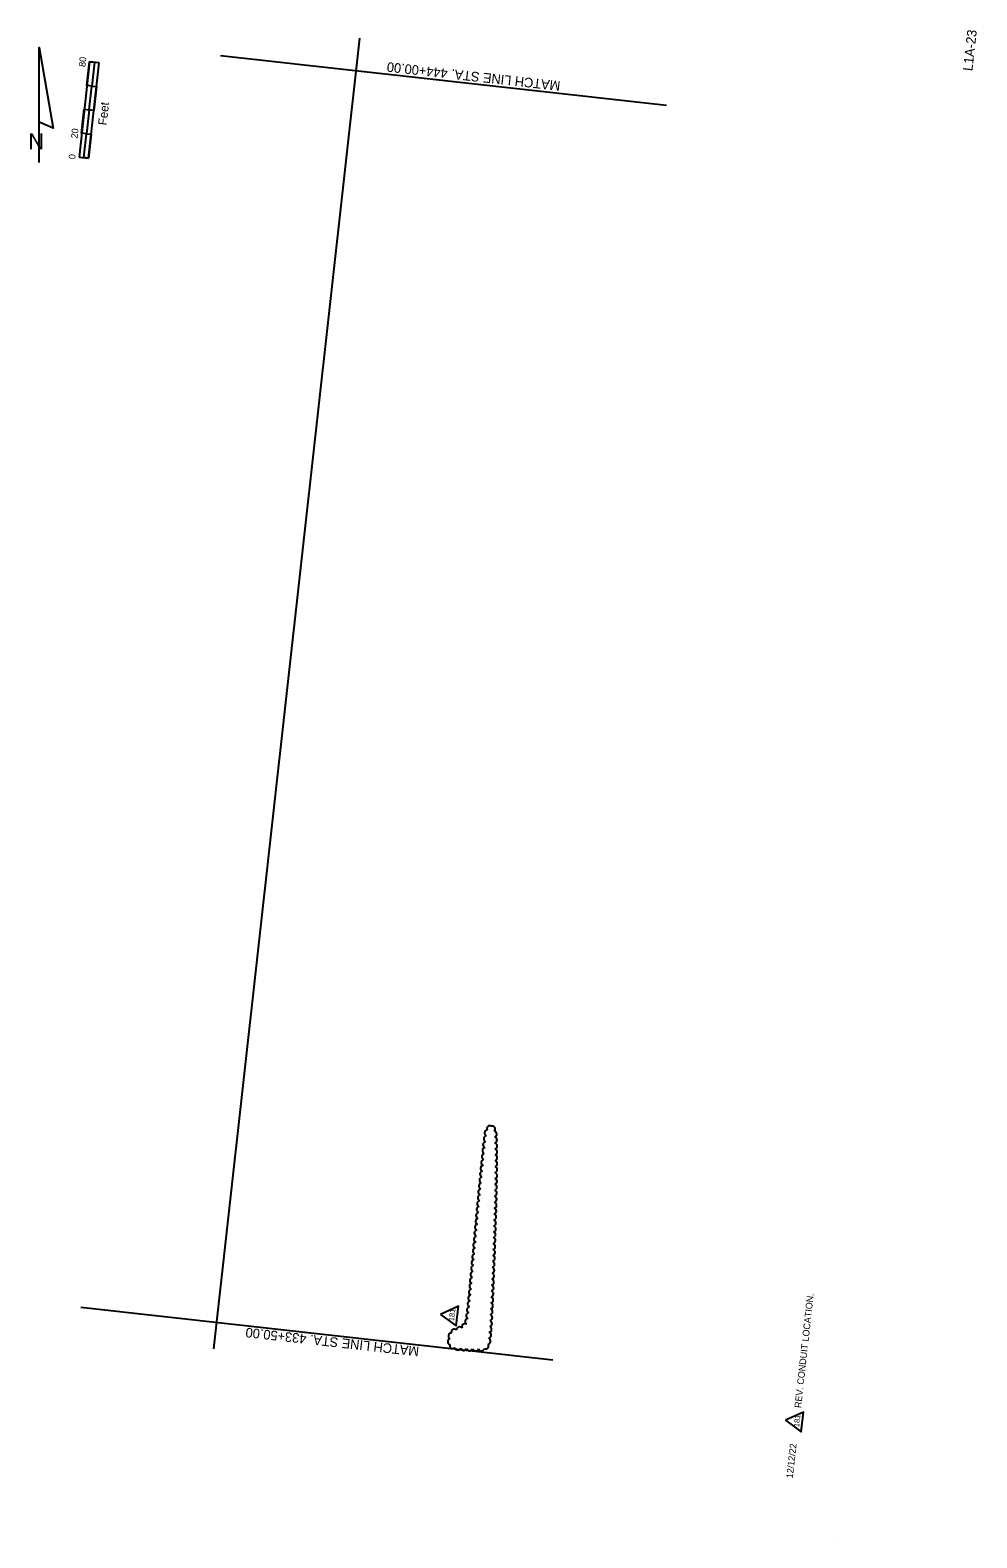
# Model space of a CAD drawing. Extents: x 930459 to 931249, y 619358 to 620615.
import ezdxf

# ---------------------------------------------------------------- set-up
doc = ezdxf.new("R2010")
doc.units = 0
for name, color, linetype in [('ActivePointCell_dp', 7, 'Continuous'), ('AdhocPoint_dp', 7, 'Continuous'), ('Cloud_dp', 7, 'Continuous'), ('MatchLines_dp', 7, 'Continuous'), ('NorthArw_dp', 7, 'Continuous'), ('Scale_dp', 7, 'Continuous'), ('TextMinor', 7, 'Continuous'), ('TextShtNo', 7, 'Continuous')]:
    doc.layers.add(name, color=color, linetype=linetype)

msp = doc.modelspace()

# ---------------------------------------------------------------- linework, layer by layer
at = {"layer": 'ActivePointCell_dp'}
msp.add_line((930612.6, 619515.8), (930734.3, 620608.2), dxfattribs=at)
at = {"layer": 'AdhocPoint_dp'}
msp.add_line((931129.5, 619358.1), (931129.5, 619358.1), dxfattribs=at)
at = {"layer": 'Cloud_dp'}
for points in [[(930801.7, 619544.4), (930814.8, 619534.9), (930816.6, 619551.3)], [(931089.4, 619456.1), (931102.5, 619446.5), (931104.3, 619463)]]:
    msp.add_lwpolyline(points, close=True, dxfattribs=at)
for centre, radius, start, end in [((930842.8, 619699.1), 2.58, 59.8581, 204.8581), ((930844.7, 619698.8), 2.59, 317.7421, 102.7421), ((930840.2, 619690.6), 2.59, 100.5209, 245.5209), ((930840.9, 619695.5), 2.59, 99.1867, 244.1867), ((930846, 619694.6), 2.59, 291.3578, 76.3578), ((930846.2, 619689.7), 2.59, 289.4145, 74.4145), ((930838.6, 619675.9), 2.59, 101.5357, 246.5357), ((930839.1, 619680.8), 2.59, 101.3357, 246.3357), ((930839.6, 619685.7), 2.59, 101.0378, 246.0378), ((930846.3, 619684.8), 2.59, 288.4557, 73.4557), ((930846.4, 619679.8), 2.59, 287.8558, 72.8558), ((930846.4, 619674.9), 2.59, 287.4349, 72.4349), ((930837.1, 619661.2), 2.59, 101.8861, 246.8861), ((930837.6, 619666.1), 2.59, 101.7952, 246.7952), ((930838.1, 619671), 2.59, 101.6821, 246.6821), ((930846.4, 619670), 2.59, 287.1185, 72.1185), ((930846.3, 619665), 2.59, 286.8694, 71.8694), ((930836.1, 619651.4), 2.59, 102.0243, 247.0243), ((930836.6, 619656.3), 2.59, 101.961, 246.961), ((930846.1, 619650.2), 2.59, 286.3538, 71.3538), ((930846.2, 619655.2), 2.59, 286.4977, 71.4977), ((930846.3, 619660.1), 2.59, 286.6668, 71.6668), ((930834.7, 619636.6), 2.59, 102.1678, 247.1678), ((930835.2, 619641.5), 2.59, 102.1261, 247.1261), ((930835.6, 619646.5), 2.59, 102.0787, 247.0787), ((930845.9, 619640.4), 2.59, 286.1205, 71.1205), ((930846, 619645.3), 2.59, 286.2294, 71.2294), ((930833.8, 619626.8), 2.59, 102.2122, 247.2122), ((930834.3, 619631.7), 2.59, 102.2046, 247.2046), ((930845.5, 619625.6), 2.59, 285.8604, 70.8604), ((930845.6, 619630.5), 2.59, 285.9379, 70.9379), ((930845.8, 619635.4), 2.59, 286.0241, 71.0241), ((930832.4, 619612.1), 2.59, 102.1791, 247.1791), ((930832.9, 619617), 2.59, 102.1912, 247.1912), ((930833.4, 619621.9), 2.59, 102.2022, 247.2022), ((930845, 619610.8), 2.59, 285.6673, 70.6673), ((930845.2, 619615.7), 2.59, 285.726, 70.726), ((930845.3, 619620.7), 2.59, 285.7901, 70.7901), ((930831.5, 619602.2), 2.59, 102.1503, 247.1503), ((930832, 619607.1), 2.59, 102.1655, 247.1655), ((930844.7, 619600.9), 2.59, 285.578, 70.578), ((930844.9, 619605.9), 2.59, 285.6211, 70.6211), ((930830.1, 619587.5), 2.59, 102.0897, 247.0897), ((930830.6, 619592.4), 2.59, 102.113, 247.113), ((930831.1, 619597.3), 2.59, 102.1329, 247.1329), ((930844.2, 619586.1), 2.59, 285.4221, 70.4221), ((930844.4, 619591.1), 2.59, 285.4792, 70.4792), ((930844.6, 619596), 2.59, 285.5309, 70.5309), ((930828.7, 619572.7), 2.59, 101.9864, 246.9864), ((930829.2, 619577.7), 2.59, 102.0285, 247.0285), ((930829.7, 619582.6), 2.59, 102.0621, 247.0621), ((930843.8, 619576.3), 2.59, 285.2876, 70.2876), ((930844, 619581.2), 2.59, 285.3587, 70.3587), ((930827.8, 619562.9), 2.59, 101.8561, 246.8561), ((930828.3, 619567.8), 2.59, 101.9317, 246.9317), ((930843.2, 619561.5), 2.59, 285.0086, 70.0086), ((930843.4, 619566.4), 2.59, 285.1152, 70.1152), ((930843.6, 619571.3), 2.59, 285.2072, 70.2072), ((930826.2, 619548.2), 2.59, 100.9456, 245.9456), ((930826.8, 619553.1), 2.59, 101.537, 246.537), ((930827.3, 619558), 2.59, 101.7419, 246.7419), ((930842.8, 619551.6), 2.59, 284.732, 69.732), ((930843, 619556.5), 2.59, 284.883, 69.883), ((930824.7, 619538.4), 2.59, 94.5308, 239.5308), ((930825.6, 619543.3), 2.59, 99.0543, 244.0543), ((930842, 619536.8), 2.59, 283.9884, 68.9884), ((930842.3, 619541.8), 2.59, 284.3076, 69.3076), ((930842.5, 619546.7), 2.59, 284.5457, 69.5457), ((930810.8, 619526.3), 2.59, 92.1634, 237.1634), ((930813.2, 619529.5), 2.59, 48.6499, 193.6499), ((930817.5, 619531.4), 2.59, 33.565, 178.565), ((930822, 619533.9), 2.59, 59.5917, 204.5917), ((930841.3, 619527), 2.59, 282.774, 67.774), ((930841.7, 619531.9), 2.59, 283.5277, 68.5277), ((930810.2, 619521.7), 2.59, 107.7005, 252.7005), ((930811.9, 619518.5), 2.59, 164.4423, 309.4423), ((930816.1, 619517.2), 2.59, 194.3604, 339.3604), ((930821, 619516.9), 2.59, 194.3604, 339.3604), ((930825.9, 619516.6), 2.59, 194.7266, 339.7266), ((930830.8, 619516.5), 2.59, 196.0083, 341.0083), ((930835.7, 619516.5), 2.59, 199.0411, 344.0411), ((930839.2, 619518.2), 2.59, 248.7643, 33.7643), ((930840.8, 619522.1), 2.59, 281.1513, 66.1513)]:
    msp.add_arc(centre, radius, start, end, dxfattribs=at)
at = {"layer": 'MatchLines_dp'}
for p, q in [((930990, 620552.2), (930618.2, 620593.6)), ((930895.3, 619506.2), (930501.8, 619550.1))]:
    msp.add_line(p, q, dxfattribs=at)
at = {"layer": 'NorthArw_dp'}
msp.add_line((930467.1, 620504.5), (930467.1, 620600.5), dxfattribs=at)
msp.add_lwpolyline([(930467.1, 620538.1), (930467.1, 620600.5), (930478.6, 620533.3)], close=True, dxfattribs=at)
at = {"layer": 'Scale_dp'}
for p, q in [((930509, 620588.6), (930500.2, 620509.1)), ((930508.2, 620508.2), (930517, 620587.7)), ((930517, 620587.7), (930509, 620588.6)), ((930500.2, 620509.1), (930508.2, 620508.2))]:
    msp.add_line(p, q, dxfattribs=at)
for points in [[(930510.8, 620568.3), (930506.8, 620568.7), (930509, 620588.6), (930513, 620588.2)], [(930512.6, 620548), (930508.6, 620548.4), (930510.8, 620568.3), (930514.8, 620567.9)], [(930506.4, 620528.5), (930502.4, 620529), (930504.6, 620548.9), (930508.6, 620548.4)], [(930508.2, 620508.2), (930504.2, 620508.7), (930506.4, 620528.5), (930510.4, 620528.1)]]:
    msp.add_lwpolyline(points, close=True, dxfattribs=at)

# ---------------------------------------------------------------- texts
at = {"layer": 'Cloud_dp'}
for p in [(930812.9, 619538.5), (931100.6, 619450.2)]:
    msp.add_text('181', height=4.5, rotation=83.6433, dxfattribs=at).set_placement(p)
at = {"layer": 'MatchLines_dp'}
for s, p in [('MATCH LINE STA. 444+00.00', (930901.9, 620572.2)), ('MATCH LINE STA. 433+50.00', (930784.1, 619517.3))]:
    msp.add_text(s, height=8, rotation=173.6425, dxfattribs=at).set_placement(p)
at = {"layer": 'NorthArw_dp'}
msp.add_text('N', height=13.4, dxfattribs=at).set_placement((930458, 620515.4))
at = {"layer": 'Scale_dp'}
for s, height, p in [('80', 5.6, (930505.5, 620584)), ('Feet', 7.2, (930523.2, 620535.3)), ('20', 5.6, (930498.9, 620524.4)), ('0', 5.6, (930497, 620507.1))]:
    msp.add_text(s, height=height, rotation=83.6844, dxfattribs=at).set_placement(p)
at = {"layer": 'TextMinor'}
for s, p in [('REV. CONDUIT LOCATION.', (931102.3, 619466.1)), ('12/12/22', (931095.4, 619407.5))]:
    msp.add_text(s, height=5.6, rotation=83.6433, dxfattribs=at).set_placement(p)
at = {"layer": 'TextShtNo'}
msp.add_text('L1A-23', height=8, rotation=83.6433, dxfattribs=at).set_placement((931245.1, 620580.5))

doc.saveas('drawing.dxf')
